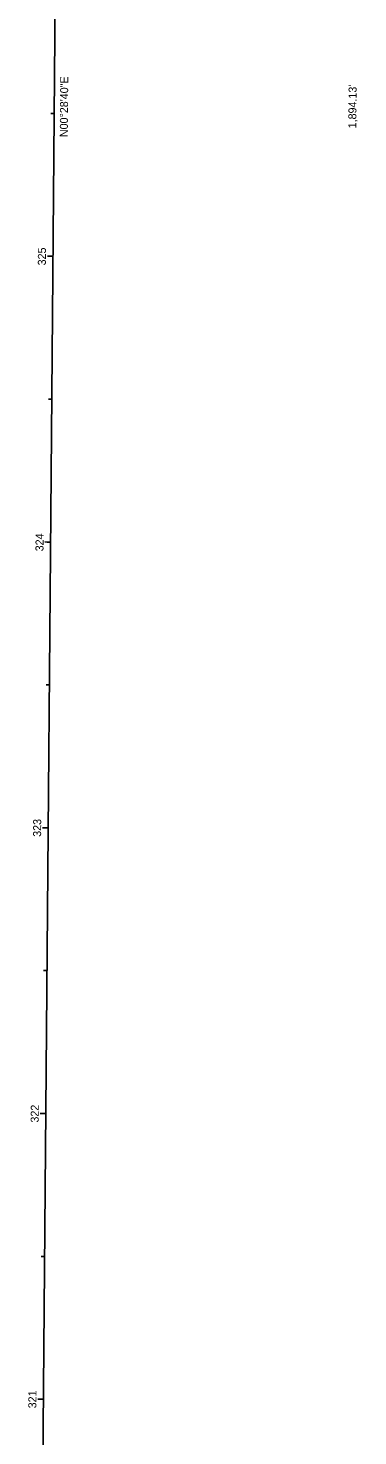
# Model space of a CAD drawing. Extents: x 1504466 to 1504712, y 322450 to 329957.
# Drawn here: x 1504597.2 to 1504712.4, y 328541.3 to 329033.9 of the extents above; entities that cross this region are included whole.
import ezdxf

# ---------------------------------------------------------------- set-up
doc = ezdxf.new("R2010")
doc.units = 0
for name, color, linetype in [('GE_X_Alignment', 7, 'Continuous'), ('GE_X_Alignment_100_Bearings', 7, 'Continuous'), ('GE_X_Alignment_100_Distances', 7, 'Continuous'), ('GE_X_Alignment_100_Stations', 7, 'Continuous'), ('GE_X_Alignment_500_Bearings', 7, 'Continuous'), ('GE_X_Alignment_500_Distances', 7, 'Continuous'), ('GE_X_Alignment_500_Stations', 7, 'Continuous')]:
    doc.layers.add(name, color=color, linetype=linetype)

msp = doc.modelspace()

# ---------------------------------------------------------------- linework, layer by layer
at = {"layer": 'GE_X_Alignment'}
msp.add_line((1504598.44, 328059.91), (1504614.24, 329953.98), dxfattribs=at)
at = {"layer": 'GE_X_Alignment_100_Stations'}
for p, q in [((1504606.32, 329004.08), (1504605.12, 329004.09)), ((1504605.9, 328954.09), (1504603.9, 328954.1)), ((1504605.48, 328904.09), (1504604.28, 328904.1)), ((1504605.07, 328854.09), (1504603.07, 328854.11)), ((1504604.65, 328804.09), (1504603.45, 328804.1)), ((1504604.23, 328754.09), (1504602.23, 328754.11)), ((1504603.81, 328704.09), (1504602.61, 328704.1)), ((1504603.4, 328654.1), (1504601.4, 328654.11)), ((1504602.98, 328604.1), (1504601.78, 328604.11)), ((1504602.56, 328554.1), (1504600.56, 328554.12))]:
    msp.add_line(p, q, dxfattribs=at)
at = {"layer": 'GE_X_Alignment_500_Stations'}
for p, q in [((1504605.9, 328954.09), (1504603.9, 328954.1)), ((1504605.07, 328854.09), (1504603.87, 328854.1)), ((1504604.23, 328754.09), (1504603.03, 328754.1)), ((1504603.4, 328654.1), (1504602.2, 328654.11)), ((1504602.56, 328554.1), (1504601.36, 328554.11))]:
    msp.add_line(p, q, dxfattribs=at)

# ---------------------------------------------------------------- texts
at = {"layer": 'GE_X_Alignment_100_Bearings'}
msp.add_text('N00°28\'40"E', height=2.8, rotation=89.5221, dxfattribs=at).set_placement((1504611.05, 328995.79))
at = {"layer": 'GE_X_Alignment_100_Distances'}
msp.add_text("1,894.13'", height=2.8, rotation=89.5221, dxfattribs=at).set_placement((1504711.91, 328998.86))
at = {"layer": 'GE_X_Alignment_100_Stations'}
for s, p in [('325', (1504603.37, 328950.9)), ('324', (1504602.54, 328850.83)), ('323', (1504601.71, 328750.92)), ('322', (1504600.87, 328650.91)), ('321', (1504600.04, 328550.9))]:
    msp.add_text(s, height=2.8, rotation=89.5221, dxfattribs=at).set_placement(p)
at = {"layer": 'GE_X_Alignment_500_Bearings'}
msp.add_text('N00°28\'40"E', height=2.8, rotation=89.5221, dxfattribs=at).set_placement((1504611.05, 328995.79))
at = {"layer": 'GE_X_Alignment_500_Distances'}
msp.add_text("1,894.13'", height=2.8, rotation=89.5221, dxfattribs=at).set_placement((1504711.91, 328998.86))
at = {"layer": 'GE_X_Alignment_500_Stations'}
msp.add_text('325', height=2.8, rotation=89.5221, dxfattribs=at).set_placement((1504603.37, 328950.9))

doc.saveas('drawing.dxf')
